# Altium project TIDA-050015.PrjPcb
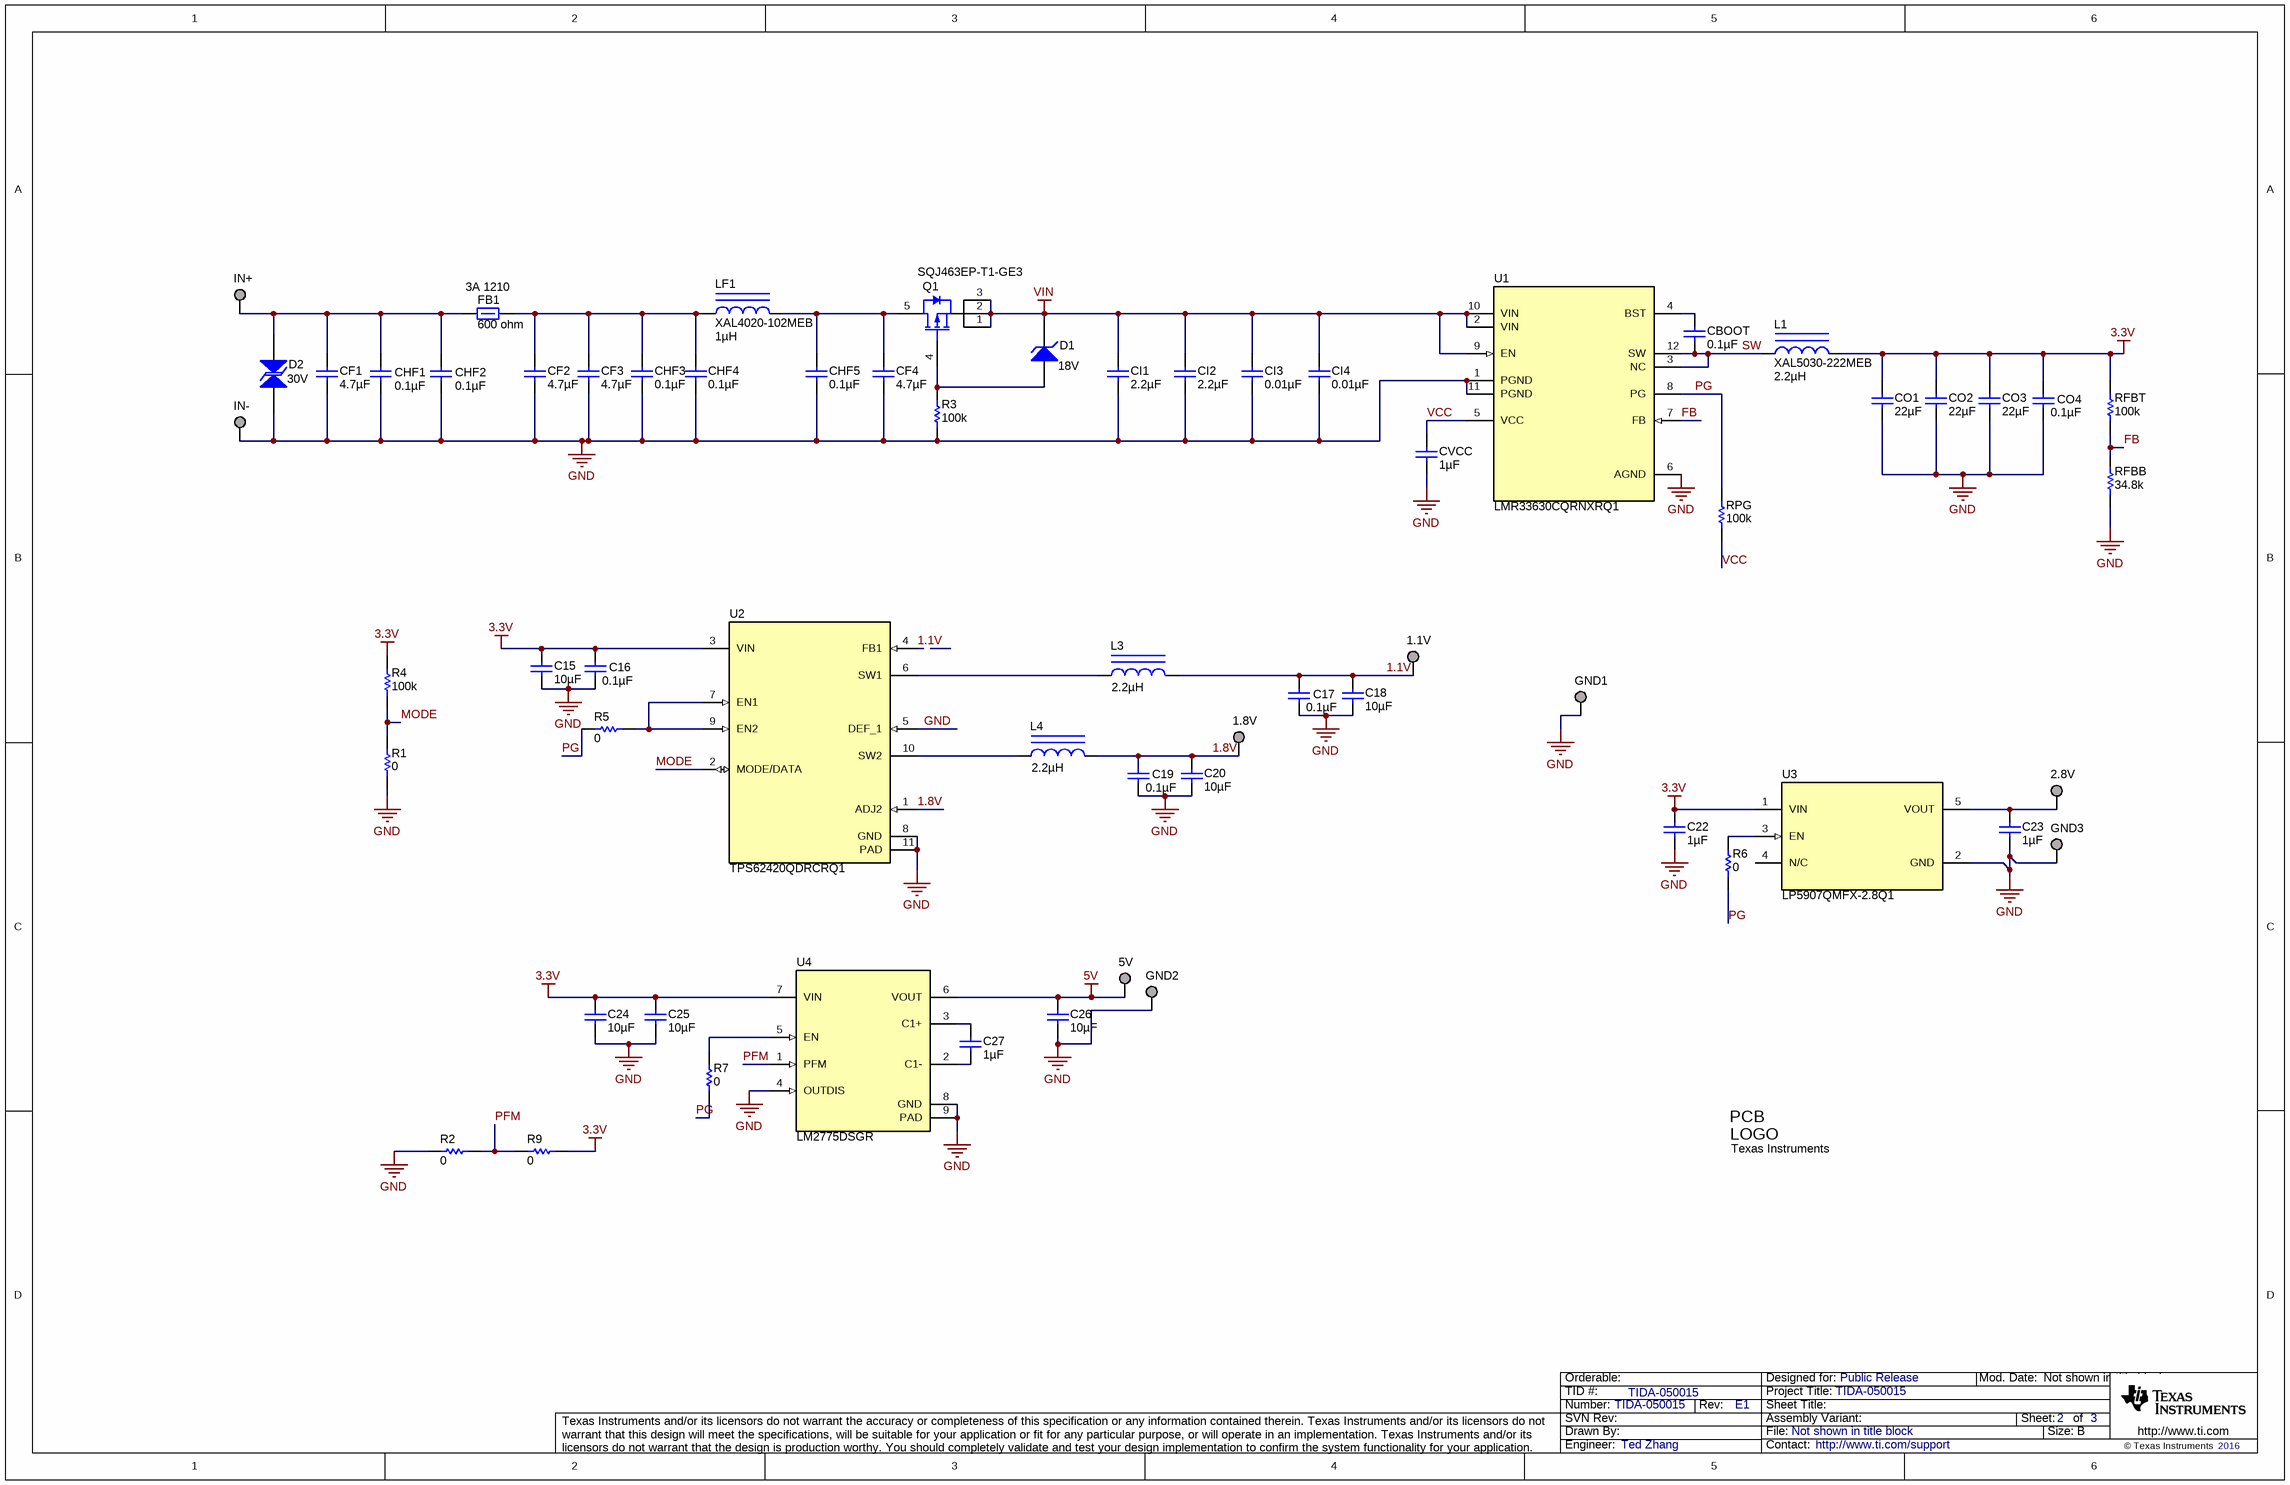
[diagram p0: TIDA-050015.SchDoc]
CopyrightYear: 2016; PCB_Layout: Ted Zhang; PCB_Rev: E1; PRJ_Customer: Public Release; PRJ_Engineer: Ted Zhang; PRJ_Number: TIDA-050015; PRJ_Title: TIDA-050015; SCH_Rev: E1; TechSupport: http://www.ti.com/support; TID: TIDA-050015
1 sheet, 64 parts. Net scope: global (net labels, ports and power ports of the same name join across sheets).
Board file: TIDA-050015.PcbDoc

## Sheet TIDA-050015.SchDoc
size 431 x 279 mm; Date: Not shown in title block; ApprovedBy: Not shown in title block; CheckedBy: Not shown in title block; Author: Not shown in title block; CompanyName: Not shown in title block; Engineer: Not shown in title block; Organization: Not shown in title block; Address1: Not shown in title block; Address2: Not shown in title block; Address3: Not shown in title block; Address4: Not shown in title block; DocumentNumber: 1; Revision: Use project parameter SCH_Rev; SheetNumber: 2; SheetTotal: 3; PageSetup: Record=PageOptions¦CenterHorizontal=True¦CenterVertical=True¦PrintScale=1.00¦XCorrection=1.00¦YCorrection=1.00¦PrintKind=0¦BorderSize=5000000¦LeftOffset=0¦BottomOffset=0¦Orientation=2¦PaperLength=1000¦PaperWidth=1000¦Scale=100¦PaperSource=15¦PrintQuality=600¦MediaType=1¦DitherType=10¦PaperKind=Letter¦PrintScaleMode=1

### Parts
1.1V  Suggest using a net name here  [Keystone1502-2]  (value not drawn)
1.8V  Suggest using a net name here  [Keystone1502-2]  (value not drawn)
2.8V  Suggest using a net name here  [Keystone1502-2]  (value not drawn)
5V  Suggest using a net name here  [Keystone1502-2]  (value not drawn)
C15  ValueDisplayed: 10µF  [0805_150]  (hidden comment: C2012X5R1A106M125AB)
C16  ValueDisplayed: 0.1µF  [0603S]  (hidden comment: GCM188R71C104KA37J)
C17  ValueDisplayed: 0.1µF  [0603S]  (hidden comment: GCM188R71C104KA37J)
C18  ValueDisplayed: 10µF  [0805_150]  (hidden comment: C2012X5R1A106M125AB)
C19  ValueDisplayed: 0.1µF  [0603S]  (hidden comment: GCM188R71C104KA37J)
C20  ValueDisplayed: 10µF  [0805_150]  (hidden comment: C2012X5R1A106M125AB)
C22  ValueDisplayed: 1µF  [0603]  (hidden comment: C0603C105K8PACTU)
C23  ValueDisplayed: 1µF  [0603]  (hidden comment: GRM188R60J105KA01D)
C24  ValueDisplayed: 10µF  [0603]  (hidden comment: C1608X5R1A106M080AC)
C25  ValueDisplayed: 10µF  [0402]  (hidden comment: CL05A106MP5NUNC)
C26  ValueDisplayed: 10µF  [0805_150]  (hidden comment: C2012X5R1A106M125AB)
C27  ValueDisplayed: 1µF  [0402]  (hidden comment: C1005JB1V105K050BC)
CBOOT  ValueDisplayed: 0.1µF  [0603]  (hidden comment: 0603YC104JAT2A)
CF1  ValueDisplayed: 4.7µF  [1210_280]  (hidden comment: CGA6P3X7R1H475M250AB)
CF2  ValueDisplayed: 4.7µF  [1210_280]  (hidden comment: CGA6P3X7R1H475M250AB)
CF3  ValueDisplayed: 4.7µF  [1210_280]  (hidden comment: CGA6P3X7R1H475M250AB)
CF4  ValueDisplayed: 4.7µF  [1210_280]  (hidden comment: CGA6P3X7R1H475M250AB)
CHF1  ValueDisplayed: 0.1µF  [0603]  (hidden comment: CGJ3E2X7R1C104K080AA)
CHF2  ValueDisplayed: 0.1µF  [0603]  (hidden comment: CGJ3E2X7R1C104K080AA)
CHF3  ValueDisplayed: 0.1µF  [0603]  (hidden comment: CGJ3E2X7R1C104K080AA)
CHF4  ValueDisplayed: 0.1µF  [0603]  (hidden comment: CGJ3E2X7R1C104K080AA)
CHF5  ValueDisplayed: 0.1µF  [0603]  (hidden comment: CGJ3E2X7R1C104K080AA)
CI1  ValueDisplayed: 2.2µF  [0805_HV]  (hidden comment: 0805YD225KAT2A)
CI2  ValueDisplayed: 2.2µF  [0805_HV]  (hidden comment: 0805YD225KAT2A)
CI3  ValueDisplayed: 0.01µF  [0402]  (hidden comment: 0402ZC103KAT2A)
CI4  ValueDisplayed: 0.01µF  [0402]  (hidden comment: 0402ZC103KAT2A)
CO1  ValueDisplayed: 22µF  [1206_180]  (hidden comment: GRM31CR71A226KE15L)
CO2  ValueDisplayed: 22µF  [1206_180]  (hidden comment: GRM31CR71A226KE15L)
CO3  ValueDisplayed: 22µF  [1206_180]  (hidden comment: GRM31CR71A226KE15L)
CO4  ValueDisplayed: 0.1µF  [0603S]  (hidden comment: GCM188R71C104KA37J)
CVCC  ValueDisplayed: 1µF  [0603]  (hidden comment: 06033C105KAT2A)
D1  value 18V  [SOD-123]  (hidden comment: MMSZ4705T1G)
D2  value 30V  [SMB-Bi]  (hidden comment: 1SMB30CAT3G)
FB1  ValueDisplayed: 600 ohm  [1210_280]  (hidden comment: FBMH3225HM601NT)
GND1  Suggest using a net name here  [Keystone1502-2]  (value not drawn)
GND2  Suggest using a net name here  [Keystone1502-2]  (value not drawn)
GND3  Suggest using a net name here  [Keystone1502-2]  (value not drawn)
IN+  Suggest using a net name here  [Keystone1502-2]  (value not drawn)
IN-  Suggest using a net name here  [Keystone1502-2]  (value not drawn)
L1  XAL5030-222MEB  ValueDisplayed: 2.2µH  [XAL5030]
L3  ValueDisplayed: 2.2µH  [LPS3015]  (hidden comment: LPS3015-222MLB)
L4  ValueDisplayed: 2.2µH  [LPS3015]  (hidden comment: LPS3015-222MLB)
LF1  XAL4020-102MEB  ValueDisplayed: 1µH  [XAL4020]
Logo1  Texas Instruments  [TI_Symbol_Overlay_Medium]  (no BOM)
Q1  SQJ463EP-T1-GE3  [PowerPAK_SO-8L]
R1  ValueDisplayed: 0  [0603]  (hidden comment: CRCW06030000Z0EA)
R2  ValueDisplayed: 0  [0603]  (hidden comment: CRCW06030000Z0EA)
R3  ValueDisplayed: 100k  [0805_HV]  (hidden comment: CRCW0805100KFKEA)
R4  ValueDisplayed: 100k  [0603]  (hidden comment: CRCW06031M00FKEA)
R5  ValueDisplayed: 0  [0402]  (hidden comment: RC0402JR-070RL)
R6  ValueDisplayed: 0  [0402]  (hidden comment: RC0402JR-070RL)
R7  ValueDisplayed: 0  [0402]  (hidden comment: RC0402JR-070RL)
R9  ValueDisplayed: 0  [0603]  (hidden comment: CRCW06030000Z0EA)
RFBB  ValueDisplayed: 34.8k  [0603]  (hidden comment: CRCW060334K8FKEA)
RFBT  ValueDisplayed: 100k  [0603]  (hidden comment: CRCW0603100KFKEA)
RPG  ValueDisplayed: 100k  [0603]  (hidden comment: CRCW0603100KFKEA)
U1  LMR33630CQRNXRQ1  [RNX0012B]
U2  TPS62420QDRCRQ1  [DRC0010J]
U3  LP5907QMFX-2.8Q1  [DBV0005A_L]
U4  LM2775DSGR  [DSG0008A]

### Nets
3.3V: C15.1 C16.1 C22.2 C24.1 C25.2 CO1.2 CO2.2 CO3.2 CO4.1 L1.2 R4.2 R9.1 RFBT.2 U2.3(VIN) U3.1(VIN) U4.7(VIN)
5V: 5V.1 C26.1 U4.6(VOUT)
GND: C15.2 C16.2 C17.2 C18.2 C19.2 C20.2 C22.1 C23.2 C24.2 C25.1 C26.2 CF1.2 CF2.2 CF3.2 CF4.2 CHF1.2 CHF2.2 CHF3.2 CHF4.2 CHF5.2 CI1.2 CI2.1 CI3.2 CI4.2 CO1.1 CO2.1 CO3.1 CO4.2 CVCC.2 D2.1 GND1.1 GND2.1 GND3.1 IN-.1 R1.1 R2.2 R3.1 RFBB.1 U1.1(PGND) U1.6(AGND) U1.11(PGND) U2.5(DEF_1) U2.8(GND) U2.11(PAD) U3.2(GND) U4.4(OUTDIS) U4.8(GND) U4.9(PAD)
VIN: CI1.1 CI2.2 CI3.1 CI4.1 D1.1(K) Q1.1(S) Q1.2(S) Q1.3(S) U1.2(VIN) U1.9(EN) U1.10(VIN)
1.1V: 1.1V.1 C17.1 C18.1 L3.2 U2.4(FB1)
1.8V: 1.8V.1 C19.1 C20.1 L4.2 U2.1(ADJ2)
FB: RFBB.2 RFBT.1 U1.7(FB)
MODE: R1.2 R4.1 U2.2(MODE/DATA)
PFM: R2.1 R9.2 U4.1(PFM)
PG: R5.1 R6.1 R7.1 RPG.2 U1.8(PG)
SW: CBOOT.2 L1.1 U1.3(NC) U1.12(SW)
VCC: CVCC.1 RPG.1 U1.5(VCC)
Net2.8V_1: 2.8V.1 C23.1 U3.5(VOUT)
NetC27_1: C27.1 U4.3(C1+)
NetC27_2: C27.2 U4.2(C1-)
NetCBOOT_1: CBOOT.1 U1.4(BST)
NetCF1_1: CF1.1 CHF1.1 CHF2.1 D2.2 FB1.1 IN+.1
NetCF2_1: CF2.1 CF3.1 CHF3.1 CHF4.1 FB1.2 LF1.1
NetCF4_1: CF4.1 CHF5.1 LF1.2 Q1.5(D)
NetD1_2: D1.2(A) Q1.4(G) R3.2
NetL3_1: L3.1 U2.6(SW1)
NetL4_1: L4.1 U2.10(SW2)
NetR5_2: R5.2 U2.7(EN1) U2.9(EN2)
NetR6_2: R6.2 U3.3(EN)
NetR7_2: R7.2 U4.5(EN)

Not connected (* = marked no-connect by the designer): U3 4(N/C)

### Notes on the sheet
- (near FB1) 3A 1210

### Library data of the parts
1.1V 1.8V 2.8V 5V GND1-GND3 IN+ IN- = 1502-2: Terminal, Turret, TH, Double; Manufacturer: Keystone; Alternate Manufacturer: Any; Alternate PartNumber: Equivalent; CompType: Turret Terminal; U/M: EA
C15 C18 C20 C26 = C2012X5R1A106M125AB: CAP, CERM, 10 µF, 10 V,+/- 20%, X5R, 0805; Manufacturer: TDK; Polarized: N; CompType: Capacitor; Value: 10uF; U/M: EA; Cap_F: 0.00001; Tolerance_%: 20; VDC_V: 10; Value2: 10V; TaMin_C: -55; TaMax_C: 85; Cap_Case: 0805; SizeArea_mm2: 2.5; SizeAreaWB_mm2: 6.75; SizeX_mm: 2; SizeY_mm: 1.25; SizeZ_mm: 1.5; AEC Category: Q200; Green_Lifecycle: EOL; Green_REACh: Passed
C16 C17 C19 CO4 = GCM188R71C104KA37J: CAP, CERM, 0.1 µF, 16 V, +/- 10%, X7R, AEC-Q200 Grade 1, 0603; Manufacturer: MuRata; Polarized: N; CompType: Capacitor; Value: 0.1uF; U/M: EA; Cap_F: 0.0000001; Tolerance_%: 10; Value1: Unknown; VDC_V: 16; Value2: 16V; TaMin_C: -55; TaMax_C: 125; Cap_Case: 0603; AEC Category: Q200; AEC Qualified: Y; AEC Grade: 1; SizeArea_mm2: 1.28; SizeAreaWB_mm2: 4.68; SizeX_mm: 1.6; SizeY_mm: 0.8
C22 = C0603C105K8PACTU: CAP, CERM, 1 µF, 10 V,+/- 10%, X5R, 0603; Manufacturer: Kemet; Polarized: N; CompType: Capacitor; Value: 1uF; U/M: EA; Cap_F: 0.000001; Tolerance_%: 10; Value2: 10V; TaMin_C: -55; TaMax_C: 85; SizeArea_mm2: 1.28; SizeAreaWB_mm2: 4.68; SizeX_mm: 1.6; SizeY_mm: 0.8; SizeZ_mm: 1; AEC Category: Q200; Green_Lifecycle: Active; Green_REACh: Passed
C23 = GRM188R60J105KA01D: CAP, CERM, 1 µF, 6.3 V,+/- 10%, X5R, 0603; Manufacturer: MuRata; Polarized: N; CompType: Capacitor; Value: 1uF; U/M: EA; Cap_F: 0.000001; Tolerance_%: 10; VDC_V: 6.3; Value2: 6.3V; TaMin_C: -55; TaMax_C: 85; SizeArea_mm2: 1.28; SizeAreaWB_mm2: 4.68; SizeX_mm: 1.6; SizeY_mm: 0.8; SizeZ_mm: 1; AEC Category: Q200; Green_Lifecycle: Active; Green_REACh: Passed
C24 = C1608X5R1A106M080AC: CAP, CERM, 10 µF, 10 V,+/- 20%, X5R, 0603; Manufacturer: TDK; Polarized: N; CompType: Capacitor; Value: 10uF; U/M: EA; Cap_F: 0.00001; Tolerance_%: 20; ESR_ohm: 0.0078; Value1: 0.0078 ohm; VDC_V: 10; Value2: 10V; IRMS_A: 1.85; TaMin_C: -55; TaMax_C: 85; SizeArea_mm2: 1.28; SizeAreaWB_mm2: 4.68; SizeX_mm: 1.6; SizeY_mm: 0.8; SizeZ_mm: 1; AEC Category: Q200; Green_Lifecycle: Active; Green_REACh: Passed
C25 = CL05A106MP5NUNC: CAP, CERM, 10 µF, 10 V,+/- 20%, X5R, 0402; Manufacturer: Samsung Electro-Mechanics; Polarized: N; CompType: Capacitor; Value: 10uF; U/M: EA; Cap_F: 0.00001; Tolerance_%: 20; VDC_V: 10; Value2: 10V; TaMin_C: -55; TaMax_C: 85; SizeArea_mm2: 0.5; SizeAreaWB_mm2: 3; SizeX_mm: 1; SizeZ_mm: 0.6; AEC Category: Q200; Green_Lifecycle: Active; Green_REACh: Passed
C27 = C1005JB1V105K050BC: CAP, CERM, 1 µF, 35 V,+/- 10%, JB, 0402; Manufacturer: TDK; Polarized: N; CompType: Capacitor; Value: 1uF; U/M: EA; Cap_F: 0.000001; Tolerance_%: 10; VDC_V: 35; Value2: 35V; TaMin_C: -25; TaMax_C: 85; SizeArea_mm2: 0.5; SizeAreaWB_mm2: 3; SizeX_mm: 1; SizeZ_mm: 0.6; AEC Category: Q200; Green_Lifecycle: Active; Green_REACh: Passed
CBOOT = 0603YC104JAT2A: CAP, CERM, 0.1 µF, 16 V,+/- 5%, X7R, 0603; Manufacturer: AVX; Polarized: N; CompType: Capacitor; Value: 0.1uF; U/M: EA; Cap_F: 0.0000001; Tolerance_%: 5; ESR_ohm: 0.039; Value1: 0.039 ohm; VDC_V: 16; Value2: 16V; TaMin_C: -55; TaMax_C: 125; SizeArea_mm2: 1.28; SizeAreaWB_mm2: 4.68; SizeX_mm: 1.6; SizeY_mm: 0.8; SizeZ_mm: 1; AEC Category: Q200; Green_Lifecycle: Active; Green_REACh: Passed
CF1-CF4 = CGA6P3X7R1H475M250AB: CAP, CERM, 4.7 µF, 50 V, +/- 20%, X7R, AEC-Q200 Grade 1, 1210; Manufacturer: TDK; Polarized: N; CompType: Capacitor; Value: 4.7uF; U/M: EA; Cap_F: 0.0000047; Tolerance_%: 20; Value1: Unknown; VDC_V: 50; Value2: 50V; TaMin_C: -55; TaMax_C: 125; Cap_Case: 1210; AEC Category: Q200; AEC Qualified: Y; AEC Grade: 1
CHF1-CHF5 = CGJ3E2X7R1C104K080AA: CAP, CERM, 0.1 µF, 16 V, +/- 10%, X7R, AEC-Q200 Grade 1, 0603; Manufacturer: TDK; Polarized: N; CompType: Capacitor; Value: 0.1uF; U/M: EA; Cap_F: 0.0000001; Tolerance_%: 10; Value1: Unknown; VDC_V: 16; Value2: 16V; TaMin_C: -55; TaMax_C: 125; AEC Category: Q200; AEC Qualified: Y; AEC Grade: 1
CI1 CI2 = 0805YD225KAT2A: CAP, CERM, 2.2 µF, 16 V,+/- 10%, X5R, 0805; Manufacturer: AVX; Polarized: N; CompType: Capacitor; Value: 2.2uF; U/M: EA; Cap_F: 0.0000022; Tolerance_%: 10; ESR_ohm: 0.009; Value1: 0.009 ohm; VDC_V: 16; Value2: 16V; TaMin_C: -55; TaMax_C: 85; Cap_Case: 0805; SizeArea_mm2: 2.5; SizeAreaWB_mm2: 6.75; SizeX_mm: 2; SizeY_mm: 1.25; SizeZ_mm: 1.45; AEC Category: Q200; Green_Lifecycle: Active; Green_REACh: Passed
CI3 CI4 = 0402ZC103KAT2A: CAP, CERM, 0.01 µF, 10 V,+/- 10%, X7R, 0402; Manufacturer: AVX; Polarized: N; CompType: Capacitor; Value: 0.01uF; U/M: EA; Cap_F: 0.00000001; Tolerance_%: 10; Value2: 10V; TaMin_C: -55; TaMax_C: 125; SizeArea_mm2: 0.5; SizeAreaWB_mm2: 3; SizeX_mm: 1; SizeZ_mm: 0.6; AEC Category: Q200
CO1-CO3 = GRM31CR71A226KE15L: CAP, CERM, 22 µF, 10 V, +/- 10%, X7R, 1206; Manufacturer: MuRata; Polarized: N; CompType: Capacitor; Value: 22uF; U/M: EA; Cap_F: 0.000022; Tolerance_%: 10; Value1: Unknown; Value2: 10V; TaMin_C: -55; TaMax_C: 125; Cap_Case: 1206; AEC Category: Q200; SizeArea_mm2: 5.12; SizeAreaWB_mm2: 10.92; SizeX_mm: 3.2; SizeY_mm: 1.6; SizeZ_mm: 1.8
CVCC = 06033C105KAT2A: CAP, CERM, 1 µF, 25 V,+/- 10%, X7R, 0603; Manufacturer: AVX; Polarized: N; CompType: Capacitor; Value: 1uF; U/M: EA; Cap_F: 0.000001; Tolerance_%: 10; VDC_V: 25; Value2: 25V; TaMin_C: -55; TaMax_C: 125; SizeArea_mm2: 1.28; SizeAreaWB_mm2: 4.68; SizeX_mm: 1.6; SizeY_mm: 0.8; SizeZ_mm: 1; AEC Category: Q200
D1 = MMSZ4705T1G: Diode, Zener, 18 V, 500 mW, SOD-123; Manufacturer: ON Semiconductor; SymbolCreator: a0412235; U/M: EA; Power_W: 0.5; Vz_V: 18; Value1: 0.5W; RJA_CperW: 340; SizeAreaWB_mm2: 13.095; SizeArea_mm2: 6.545; SizeX_mm: 3.85; SizeY_mm: 1.7; SizeZ_mm: 1.35; AEC Category: Q101
D2 = 1SMB30CAT3G: Diode, TVS, Bi, 30 V, 48.4 Vc, SMB; Manufacturer: ON Semiconductor; U/M: EA; Power_W: 3; Vr_V: 30; Value1: 3W; AEC Category: Q101
FB1 = FBMH3225HM601NT: Ferrite Bead, 600 ohm @ 100 MHz, 3 A, 1210; Manufacturer: Taiyo Yuden; Value: 600 ohm; Imax_A: 3; DCR_ohm: 0.042; Value1: 0.042 ohm; Value2: 3A; SizeAreaWB_mm2: 14.7; SizeArea_mm2: 8; SizeX_mm: 3.2; SizeY_mm: 2.5; SizeZ_mm: 2.8; ZTyp@100MHz_Ohm: 600; Green_Lifecycle: Active; Green_REACh: Passed
L1 = XAL5030-222MEB: Inductor, Shielded, Composite, 2.2uH, 9.2A, 0.01 ohm, SMD; Manufacturer: Coilcraft; Ind_H: 2.2E-6; Imax_A: 9.2; Irms: 9.2A @ 40C rise; Isat: 12.9A @ 30% inductance drop; DCR_ohm: 0.01; U/M: EA
L3 L4 = LPS3015-222MLB: Inductor, Shielded Drum Core, Ferrite, 2.2uH, 1.4A, 0.11 ohm, SMD; Manufacturer: Coilcraft; Ind_H: 2.2E-6; Imax_A: 1.4; Irms: 1.4A @ 40C rise; Isat: 2.1A @ 30% inductance drop; DCR_ohm: 0.11; U/M: EA
LF1 = XAL4020-102MEB: Inductor, Shielded, Composite, 1uH, 8.75A, 0.01 ohm, SMD; Manufacturer: Coilcraft; Ind_H: 1.0E-6; Imax_A: 8.75; Irms: 9.6A @ 40C rise; Isat: 8.75A @ 30% inductance drop; DCR_ohm: 0.01; U/M: EA
Logo1 = TI_Logo: Texas Instrument Corporate Signature; SymbolCreator: codlsc
Q1 = SQJ463EP-T1-GE3: MOSFET, P-CH, -40 V, -30 A, PowerPAK_SO-8L; Manufacturer: Vishay-Siliconix; Alternate Manufacturer: None; SymbolCreator: a0411947; U/M: EA; ChType: P; Value: -40V; Value1: 0.015 ohm; Rdson45_ohm: 0.015; Value2: 98 nC; QgTyp_nC: 98; Vgs_V: -20; SizeAreaWB_mm2: 58.1095; SizeArea_mm2: 31.5495; SizeX_mm: 6.15; SizeY_mm: 5.13; SizeZ_mm: 1.14; AEC Category: Q101; Green_Lifecycle: Not Set; Green_REACh: Incomplete
R1 R2 R9 = CRCW06030000Z0EA: RES, 0, 5%, 0.1 W, 0603; Manufacturer: Vishay-Dale; CompType: Resistor; Value: 0; Value_Code: 0000; Tolerance_%: 5; Power_W: 0.1; Value2: 0.1W; VDC_V: 75; TempCo: 200 ppm/C; SizeArea_mm2: 1.28; SizeX_mm: 1.6; SizeY_mm: 0.8; SizeZ_mm: 1; EIA_Code: E24; U/M: EA; AEC Category: Q200; Green_Lifecycle: Active; Green_REACh: Passed
R3 = CRCW0805100KFKEA: RES, 100 k, 1%, 0.125 W, 0805; Manufacturer: Vishay-Dale; CompType: Resistor; Value: 100k; Res_ohm: 100000; Tolerance_%: 1; Power_W: 0.125; Value2: 0.125W; VDC_V: 150; TempCo: 100 ppm/C; SizeArea_mm2: 2.5; SizeX_mm: 2; SizeY_mm: 1.25; SizeZ_mm: 1.45; EIA_Code: E96; U/M: EA; AEC Category: Q200; Green_Lifecycle: Active; Green_REACh: Passed
R4 = CRCW06031M00FKEA: RES, 1.00 M, 1%, 0.1 W, 0603; Manufacturer: Vishay-Dale; CompType: Resistor; Value: 1.00Meg; Res_ohm: 1000000; Value_Code: 1M00; Tolerance_%: 1; Power_W: 0.1; Value2: 0.1W; VDC_V: 75; TempCo: 100 ppm/C; EIA_Code: E96; U/M: EA; AEC Category: Q200
R5-R7 = RC0402JR-070RL: RES, 0, 5%, 0.063 W, 0402; Manufacturer: Yageo America; CompType: Resistor; Value: 0; Value_Code: 0000; Tolerance_%: 5; Power_W: 0.063; Value2: 0.063W; VDC_V: 50; TempCo: 200 ppm/C; SizeArea_mm2: 0.5; SizeX_mm: 1; SizeZ_mm: 0.6; EIA_Code: E24; U/M: EA; AEC Category: Q200; Green_Lifecycle: Active; Green_REACh: Passed
RFBB = CRCW060334K8FKEA: RES, 34.8 k, 1%, 0.1 W, 0603; Manufacturer: Vishay-Dale; CompType: Resistor; Value: 34.8k; Res_ohm: 34800; Value_Code: 34k8; Tolerance_%: 1; Power_W: 0.1; Value2: 0.1W; VDC_V: 75; TempCo: 100 ppm/C; SizeArea_mm2: 1.28; SizeX_mm: 1.6; SizeY_mm: 0.8; EIA_Code: E96; U/M: EA; AEC Category: Q200; Green_Lifecycle: Active; Green_REACh: Passed
RFBT = CRCW0603100KFKEA: RES, 100 k, 1%, 0.1 W, 0603; Manufacturer: Vishay-Dale; CompType: Resistor; Value: 100k; Res_ohm: 100000; Tolerance_%: 1; Power_W: 0.1; Value2: 0.1W; VDC_V: 75; TempCo: 100 ppm/C; SizeArea_mm2: 1.28; SizeX_mm: 1.6; SizeY_mm: 0.8; EIA_Code: E96; U/M: EA; AEC Category: Q200; Green_Lifecycle: Active; Green_REACh: Passed
RPG = CRCW0603100KFKEA: RES, 100 k, 1%, 0.1 W, 0603; Manufacturer: Vishay-Dale; CompType: Resistor; Value: 100k; Res_ohm: 100000; Tolerance_%: 1; Power_W: 0.1; Value2: 0.1W; VDC_V: 75; TempCo: 100 ppm/C; EIA_Code: E96; U/M: EA
U1 = CMP-0078599-3: Automotive 3.8-V to 36-V 3-A Synchronous Step-Down Voltage Regulator, RNX0012B (VQFN-HR-12); Alternate PartNumber: LMR33630CQRNXTQ1; Alternate Manufacturer: Texas Instruments; SizeAreaWB_mm2: 12.0; SizeZ_mm: 1.0; SizeX_mm: 2.0; SizeY_mm: 3.0; SizeArea_mm2: 6.0; CompType: IC; AEC Qualified: Y; AEC Category: Q200
U2 = CMP-0074044-4: Automotive 2.5V to 6V, 2.25MHz Fixed Frequency Dual (1A/600mA) Buck Converter with 1-Wire Interface, DRC0010J (VSON-10); Manufacturer: Texas Instruments; SizeZ_mm: 1; SizeX_mm: 3; SizeArea_mm2: 9; CompType: IC; SizeAreaWB_mm2: 16; AEC Category: Q200; AEC Qualified: Y
U3 = CMP-0076240-1: Automotive 250-mA, Ultra-Low-Noise, Low-IQ LDO, DBV0005A (SOT-23-5); Manufacturer: Texas Instruments; SizeAreaWB_mm2: 14.82; SizeArea_mm2: 8.12; SizeZ_mm: 1.45; SizeY_mm: 2.9; U/M: EA; CompType: IC; SizeX_mm: 2.8
U4 = LM2775DSGR: Switched Capacitor 5V Boost Converter, DSG0008A (WSON-8); Alternate PartNumber: LM2775DSGT; Manufacturer: Texas Instruments; SymbolCreator: Altium; SizeArea_mm2: 4; SizeAreaWB_mm2: 9; SizeX_mm: 2; SizeZ_mm: 0.8; CompType: IC; U/M: EA; Green_Lifecycle: Active; Green_REACh: Passed

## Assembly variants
001: not fitted FID1 FID2 FID3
